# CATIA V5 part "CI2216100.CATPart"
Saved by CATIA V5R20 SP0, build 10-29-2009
Part number: CI2216100
Bounding box of the stored display mesh (mm): x -15 to 15, y -10.788 to 124, z -21.241 to 16.291
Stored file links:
  C:\Users\Raffaele\Desktop\3D X SITO CF\BOLEX\19-INCLINED ASSEMBLY REF_CI\CI2216100.CATPart
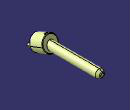
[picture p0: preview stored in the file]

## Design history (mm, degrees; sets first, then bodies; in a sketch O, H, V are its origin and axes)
Set1
  DatumSurface1 to DatumSurface16 "MANIFOLD_SOLID_BREP #385"
  DatumSurface17 to DatumSurface39 "MANIFOLD_SOLID_BREP #1143"
Body1 (main body)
